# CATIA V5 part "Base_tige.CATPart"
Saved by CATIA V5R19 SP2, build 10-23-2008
Part number: Base_tige
Bounding box of the stored display mesh (mm): x 0 to 10, y -15 to 15, z -14.996 to 14.996
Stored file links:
  C:\Users\Romain\Documents\IFMA\2A\cours\S3\Projet CFAO-IAO\IAO\Catia\Tige\Base_tige.CATPart
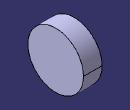
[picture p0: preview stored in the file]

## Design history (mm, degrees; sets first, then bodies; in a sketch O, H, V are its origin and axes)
Body1 (main body)
  Sketch1 on yz-plane, origin (0, 0, 0), H (0, 1, 0), V (0, 0, 1)
    circle A1 centre (0, 0) radius 15
    radius A1 = 15
  Pad1: profile Sketch1, direction (1, 0, 0), length 10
